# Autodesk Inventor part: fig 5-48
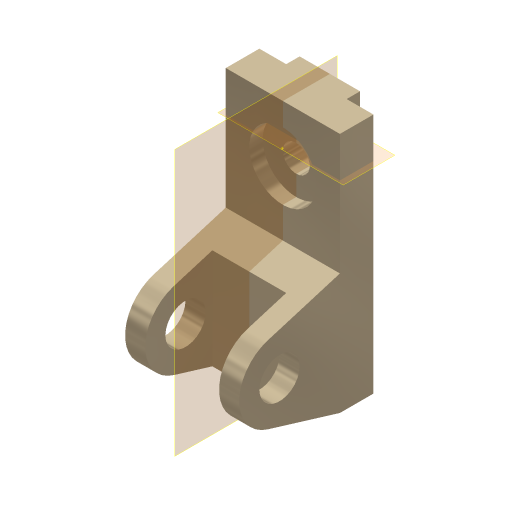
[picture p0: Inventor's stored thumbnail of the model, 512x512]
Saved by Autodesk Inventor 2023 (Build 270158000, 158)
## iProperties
Created: 2001-11
Part Number: fig 5-48
Document SubType Name: Modeling
Designer: Renu Muthoo
Density: 1 g/cm^3
Material: Generic
Appearance: Metal-Titanium (Polished)
Control State: 0
Master: False
Checked Out: False
Shininess: 65.0
Angle Display Precision: 2
Document Length Units: 11269
Document Angle Units: 11279
Document Time Units: 11290
Document Mass Units: 11283
Document Length Units Precision: 3
Document Angle Units Precision: 2
Density: 0.0
Volumn: 0.0
Area: 0.0
PropertySet Name: Model Information
Author: Renu Muthoo
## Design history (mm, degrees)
node "Sketch1"
sketch "Sketch2"
  geometry: L1 (33.257, 104.664)-(33.257, -75.336); L2 (33.257, -75.336)-(8.257, -75.336); L3 (8.257, -75.336)-(-45.451, -59.045); L4 (-45.451, -1.628)-(8.257, 14.664); L5 (8.257, 14.664)-(8.257, 104.664); L6 (8.257, 104.664)-(33.257, 104.664); C1 r 15 at (-36.743, -30.336); A1 r 30 centre (-36.743, -30.336) between (-45.451, -1.628) and (-45.451, -59.045)
  constraints: 12 end point, 2 centre point, 2 equal length, 2 parallel, 2 point on circle, 2 tangent, 1 coincident, 1 perpendicular, 1 vertical
  dimensions: "d0" = 180 distance of L1.start L1.end; "d1" = 30 radius of A1; "d2" = 25 distance of L5.end L1.start; "d3" = 45 distance from line of L2 A1.centre; "d4" = 70 distance from line of L1 A1.centre; "d5" = 30 diameter of C1
extrude "Extrusion1" new body sketch "Sketch2" distance "d6" = 85; taper "d7" = 0 deg
workplane "Work Plane1"
sketch "Sketch3"
  geometry: L1 (15, 62.364)-(70, 62.364); L2 (70, 62.364)-(70, -52.386); L3 (70, -52.386)-(15, -52.386); L4 (15, -52.386)-(15, 62.364); L5 (0, -45)-(0, -28.708) reference
  constraints: 8 end point, 2 parallel, 1 horizontal, 1 perpendicular
  dimensions: "d8" = 55 distance of L1.start L1.end; "d9" = 15 distance between parallel lines of L5 L4
extrude "Extrusion2" cut sketch "Sketch3" distance "d10" = 50; taper "d11" = 0 deg
sketch "Sketch4"
  geometry: L1 (0, 25)-(85, 25) reference; L2 (0, 0)-(0, 25) reference; L3 (20, 25)-(65, 25); L4 (65, 25)-(65, 35); L5 (65, 35)-(20, 35); L6 (20, 35)-(20, 25)
  constraints: 8 end point, 2 parallel, 1 horizontal, 1 perpendicular, 1 point on line
  dimensions: "d12" = 45 distance of L4.end L5.end; "d13" = 10 distance of L3.end L4.end; "d14" = 20 distance between parallel lines of L2 L6
extrude "Extrusion3" join sketch "Sketch4" stored distance "d15" = 50; taper "d16" = 0 deg
sketch "Sketch5"
  geometry: L1 (85, 0)-(85, 90) reference; L2 (0, 90)-(85, 90) reference; 1 further point
  dimensions: "d17" = 42 distance from line of L2 point (42.5, 48); "d18" = 42.5 distance from line of L1 point (42.5, 48)
hole "Hole1" sketch "Sketch5" at (42.5, 48) diameter "d19" = 20; stored, may be unused: countersink angle "d23" = 82 deg, drill point angle "d25" = 118 deg; dims "d20" = 6, "d21" = 50, "d22" = 10, "d24" = 8
workpoint "Work Point9"
  workplane "Work Plane8"
  workplane "Work Plane12"
body "Solid1"
